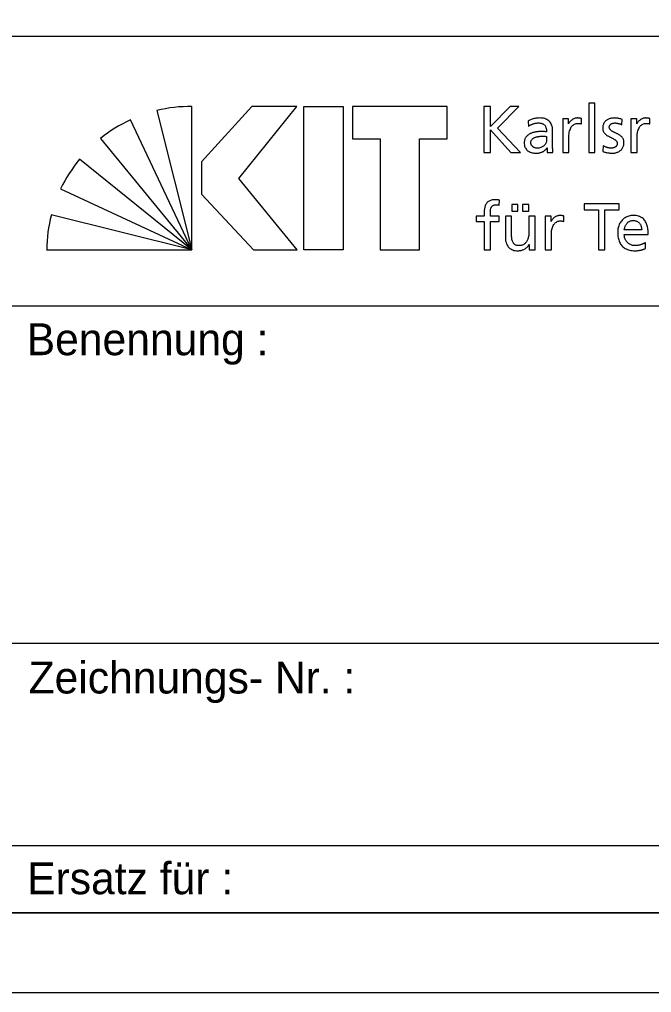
# Model space of a CAD drawing. Extents: x 0 to 297, y 0 to 210.
# Drawn here: x 275.16 to 285.08, y 0 to 15.26 of the extents above; entities that cross this region are included whole.
import ezdxf

# ---------------------------------------------------------------- set-up
doc = ezdxf.new("R2010")
doc.units = 0
doc.layers.add('90_Plankopf', color=7, linetype='Continuous')

msp = doc.modelspace()

# ---------------------------------------------------------------- linework, layer by layer
at = {"layer": '90_Plankopf'}
for p, q in [((251.53, 14.998), (296, 14.998)), ((251.53, 14.998), (296, 14.998)), ((277.87, 11.647), (277.87, 13.896)), ((282.452, 13.897), (282.452, 13.176)), ((277.319, 13.833), (277.87, 11.647)), ((277.87, 11.647), (276.908, 13.688)), ((283.145, 13.665), (283.15, 13.583)), ((283.982, 13.621), (283.982, 13.708)), ((284.614, 13.61), (284.622, 13.694)), ((285.053, 13.621), (285.053, 13.708)), ((283.53, 13.28), (283.53, 13.497)), ((276.436, 13.396), (277.87, 11.647)), ((283.433, 13.427), (283.433, 13.381)), ((284.324, 13.28), (284.319, 13.193)), ((282.452, 13.176), (282.556, 13.176)), ((282.876, 13.176), (283.027, 13.176)), ((277.87, 11.647), (276.108, 13.071)), ((275.81, 12.603), (277.87, 11.647)), ((282.693, 12.348), (282.697, 12.427)), ((277.87, 11.647), (275.664, 12.197)), ((283.707, 12.091), (283.707, 12.178)), ((284.927, 11.96), (284.654, 11.96)), ((284.654, 11.888), (285.03, 11.888)), ((284.989, 11.668), (284.989, 11.765)), ((275.591, 11.647), (277.87, 11.647)), ((275, 10.768), (296, 10.768)), ((275, 5.48), (296, 5.48)), ((275, 2.308), (296, 2.308)), ((296, 1.25), (251.53, 1.25)), ((254.45, 1.25), (296, 1.25)), ((254.45, 1.25), (296, 1.25))]:
    msp.add_line(p, q, dxfattribs=at)
for points in [[(0, 0), (297.25, 0), (297.25, 210.25), (0, 210.25)], [(6.25, 1.25), (296, 1.25), (296, 209), (6.25, 209)], [(279.517, 13.897), (278.809, 13.897), (278.018, 13.025), (278.018, 12.523), (278.834, 11.647), (279.521, 11.647), (278.606, 12.766)], [(280.243, 13.897), (280.243, 11.647), (279.625, 11.647), (279.625, 13.897)], [(280.391, 13.897), (280.391, 13.39), (280.825, 13.39), (280.825, 11.647), (281.443, 11.647), (281.443, 13.39), (281.877, 13.39), (281.877, 13.897)]]:
    msp.add_lwpolyline(points, close=True, dxfattribs=at)
for points in [[(283.027, 13.176), (282.662, 13.556), (283, 13.897), (282.863, 13.897), (282.556, 13.58), (282.556, 13.897), (282.452, 13.897)], [(284.095, 13.176), (284.192, 13.176), (284.192, 13.95), (284.095, 13.95), (284.095, 13.176)], [(283.78, 13.621), (283.778, 13.621), (283.778, 13.703), (283.688, 13.703), (283.688, 13.176), (283.785, 13.176), (283.785, 13.416)], [(284.852, 13.621), (284.85, 13.621), (284.85, 13.703), (284.759, 13.703), (284.759, 13.176), (284.856, 13.176), (284.856, 13.416)], [(282.556, 13.176), (282.556, 13.529), (282.876, 13.176)], [(283.441, 13.245), (283.443, 13.245), (283.443, 13.176), (283.534, 13.176)], [(284.248, 11.647), (284.351, 11.647), (284.351, 12.276), (284.575, 12.276), (284.575, 12.367), (284.024, 12.367), (284.024, 12.276), (284.248, 12.276), (284.248, 11.647)], [(282.456, 12.221), (282.456, 12.173), (282.332, 12.173), (282.332, 12.094), (282.456, 12.094), (282.456, 11.647), (282.553, 11.647), (282.553, 12.094), (282.692, 12.094), (282.692, 12.173), (282.553, 12.173), (282.553, 12.23)], [(282.889, 12.356), (282.889, 12.253), (282.986, 12.253), (282.986, 12.356), (282.889, 12.356)], [(283.058, 12.356), (283.058, 12.253), (283.155, 12.253), (283.155, 12.356), (283.058, 12.356)], [(282.885, 11.9), (282.885, 12.173), (282.788, 12.173), (282.788, 11.86)], [(283.254, 11.647), (283.254, 12.173), (283.157, 12.173), (283.157, 11.929)], [(283.506, 12.091), (283.504, 12.091), (283.504, 12.173), (283.413, 12.173), (283.413, 11.647), (283.51, 11.647), (283.51, 11.886)], [(283.158, 11.73), (283.16, 11.73), (283.16, 11.647), (283.254, 11.647)]]:
    msp.add_lwpolyline(points, dxfattribs=at)
for centre, start, end in [((277.862, 11.514), 89.8053, 103.1895), ((277.915, 11.529), 115.0126, 128.3968), ((277.954, 11.566), 140.7898, 154.174), ((277.973, 11.609), 165.7222, 179.1064)]:
    msp.add_arc(centre, 2.382, start, end, dxfattribs=at)
for points in [[(283.53, 13.497), (283.53, 13.545), (283.523, 13.585), (283.508, 13.617), (283.494, 13.65), (283.471, 13.674), (283.44, 13.69), (283.409, 13.707), (283.368, 13.715), (283.318, 13.715), (283.285, 13.715), (283.253, 13.71), (283.224, 13.701), (283.195, 13.692), (283.169, 13.68), (283.145, 13.665)], [(283.15, 13.583), (283.163, 13.594), (283.178, 13.604), (283.195, 13.611), (283.211, 13.62), (283.229, 13.626), (283.247, 13.63), (283.266, 13.634), (283.284, 13.637), (283.303, 13.637), (283.335, 13.637), (283.36, 13.631), (283.379, 13.621), (283.399, 13.611), (283.412, 13.596), (283.42, 13.575), (283.429, 13.555), (283.433, 13.53), (283.433, 13.499)], [(283.982, 13.708), (283.975, 13.709), (283.968, 13.71), (283.962, 13.712), (283.956, 13.713), (283.949, 13.713), (283.942, 13.714), (283.935, 13.715), (283.927, 13.715), (283.918, 13.715), (283.899, 13.715), (283.881, 13.711), (283.863, 13.703), (283.845, 13.695), (283.829, 13.684), (283.815, 13.67), (283.801, 13.656), (283.789, 13.639), (283.78, 13.621)], [(283.785, 13.416), (283.785, 13.46), (283.791, 13.498), (283.802, 13.53), (283.814, 13.562), (283.831, 13.587), (283.852, 13.604), (283.874, 13.621), (283.899, 13.63), (283.928, 13.63), (283.936, 13.631), (283.945, 13.63), (283.954, 13.629), (283.964, 13.627), (283.973, 13.625), (283.982, 13.621)], [(284.622, 13.694), (284.604, 13.7), (284.584, 13.705), (284.565, 13.709), (284.545, 13.713), (284.524, 13.715), (284.502, 13.715), (284.476, 13.715), (284.451, 13.712), (284.429, 13.705), (284.406, 13.698), (284.387, 13.688), (284.37, 13.675), (284.353, 13.662), (284.34, 13.645), (284.33, 13.625), (284.321, 13.604), (284.316, 13.58), (284.316, 13.553), (284.316, 13.532), (284.321, 13.514), (284.329, 13.498), (284.337, 13.483), (284.348, 13.47), (284.361, 13.459), (284.375, 13.447), (284.39, 13.437), (284.406, 13.429), (284.422, 13.42), (284.438, 13.412), (284.454, 13.404), (284.471, 13.397), (284.485, 13.389), (284.499, 13.38), (284.512, 13.373), (284.523, 13.363), (284.532, 13.353), (284.54, 13.343), (284.544, 13.331), (284.544, 13.318), (284.544, 13.304), (284.541, 13.292), (284.535, 13.282), (284.529, 13.272), (284.521, 13.265), (284.511, 13.259), (284.501, 13.253), (284.491, 13.249), (284.479, 13.246), (284.468, 13.244), (284.456, 13.242), (284.445, 13.242), (284.435, 13.242), (284.424, 13.244), (284.41, 13.247), (284.396, 13.249), (284.381, 13.253), (284.366, 13.259), (284.351, 13.265), (284.337, 13.271), (284.324, 13.28)], [(284.319, 13.193), (284.342, 13.181), (284.365, 13.174), (284.389, 13.17), (284.414, 13.166), (284.439, 13.164), (284.464, 13.164), (284.487, 13.164), (284.51, 13.167), (284.532, 13.174), (284.554, 13.18), (284.573, 13.191), (284.591, 13.204), (284.608, 13.217), (284.622, 13.234), (284.632, 13.255), (284.642, 13.276), (284.647, 13.3), (284.647, 13.328), (284.647, 13.352), (284.643, 13.372), (284.635, 13.389), (284.626, 13.406), (284.616, 13.42), (284.602, 13.431), (284.589, 13.443), (284.574, 13.453), (284.557, 13.461), (284.541, 13.469), (284.525, 13.477), (284.509, 13.484), (284.493, 13.491), (284.478, 13.499), (284.464, 13.507), (284.451, 13.515), (284.44, 13.524), (284.432, 13.534), (284.424, 13.545), (284.419, 13.557), (284.419, 13.573), (284.419, 13.587), (284.424, 13.599), (284.432, 13.609), (284.441, 13.618), (284.452, 13.625), (284.466, 13.63), (284.48, 13.634), (284.495, 13.637), (284.512, 13.637), (284.518, 13.637), (284.526, 13.636), (284.535, 13.634), (284.544, 13.633), (284.553, 13.631), (284.564, 13.628), (284.574, 13.626), (284.583, 13.623), (284.592, 13.62), (284.601, 13.616), (284.609, 13.613), (284.614, 13.61)], [(285.053, 13.708), (285.046, 13.709), (285.04, 13.71), (285.034, 13.712), (285.027, 13.713), (285.021, 13.713), (285.014, 13.714), (285.007, 13.715), (284.998, 13.715), (284.989, 13.715), (284.97, 13.715), (284.952, 13.711), (284.934, 13.703), (284.917, 13.695), (284.901, 13.684), (284.886, 13.67), (284.872, 13.656), (284.86, 13.639), (284.852, 13.621)], [(284.856, 13.416), (284.856, 13.46), (284.862, 13.498), (284.874, 13.53), (284.886, 13.562), (284.902, 13.587), (284.923, 13.604), (284.945, 13.621), (284.97, 13.63), (284.999, 13.63), (285.008, 13.631), (285.016, 13.63), (285.026, 13.629), (285.035, 13.627), (285.044, 13.625), (285.053, 13.621)], [(283.433, 13.499), (283.42, 13.5), (283.408, 13.501), (283.397, 13.501), (283.386, 13.501), (283.376, 13.501), (283.365, 13.501), (283.354, 13.501), (283.342, 13.501), (283.329, 13.501), (283.309, 13.501), (283.288, 13.5), (283.266, 13.496), (283.243, 13.492), (283.221, 13.487), (283.2, 13.478), (283.179, 13.47), (283.16, 13.46), (283.142, 13.446), (283.125, 13.433), (283.111, 13.416), (283.101, 13.397), (283.09, 13.377), (283.085, 13.354), (283.085, 13.328), (283.085, 13.29), (283.094, 13.259), (283.11, 13.235), (283.126, 13.211), (283.149, 13.193), (283.177, 13.181), (283.206, 13.17), (283.24, 13.164), (283.278, 13.164), (283.3, 13.164), (283.32, 13.167), (283.338, 13.172), (283.355, 13.177), (283.371, 13.184), (283.384, 13.192), (283.398, 13.2), (283.409, 13.209), (283.418, 13.218), (283.428, 13.228), (283.435, 13.236), (283.441, 13.245)], [(283.433, 13.381), (283.433, 13.354), (283.427, 13.331), (283.416, 13.31), (283.405, 13.289), (283.388, 13.273), (283.367, 13.261), (283.345, 13.249), (283.318, 13.243), (283.286, 13.242), (283.275, 13.242), (283.264, 13.244), (283.252, 13.248), (283.241, 13.252), (283.23, 13.257), (283.22, 13.264), (283.211, 13.272), (283.203, 13.281), (283.197, 13.291), (283.191, 13.302), (283.188, 13.314), (283.188, 13.328), (283.188, 13.347), (283.193, 13.362), (283.202, 13.374), (283.211, 13.387), (283.223, 13.396), (283.237, 13.404), (283.252, 13.411), (283.267, 13.417), (283.284, 13.42), (283.3, 13.424), (283.316, 13.426), (283.332, 13.428), (283.347, 13.429), (283.36, 13.429), (283.371, 13.429), (283.381, 13.429), (283.391, 13.429), (283.402, 13.428), (283.412, 13.428), (283.422, 13.427), (283.433, 13.427)], [(283.534, 13.176), (283.533, 13.181), (283.532, 13.188), (283.532, 13.197), (283.531, 13.205), (283.531, 13.216), (283.53, 13.23), (283.53, 13.243), (283.53, 13.26), (283.53, 13.28)], [(282.697, 12.427), (282.688, 12.428), (282.678, 12.43), (282.667, 12.431), (282.656, 12.432), (282.645, 12.433), (282.632, 12.433), (282.597, 12.433), (282.568, 12.428), (282.544, 12.418), (282.521, 12.408), (282.503, 12.394), (282.491, 12.375), (282.478, 12.356), (282.469, 12.334), (282.464, 12.308), (282.458, 12.282), (282.456, 12.253), (282.456, 12.221)], [(282.553, 12.23), (282.553, 12.247), (282.554, 12.264), (282.556, 12.279), (282.558, 12.294), (282.562, 12.307), (282.569, 12.319), (282.575, 12.33), (282.585, 12.339), (282.597, 12.345), (282.61, 12.351), (282.626, 12.354), (282.647, 12.354), (282.655, 12.354), (282.664, 12.354), (282.672, 12.353), (282.68, 12.352), (282.688, 12.35), (282.693, 12.348)], [(283.707, 12.178), (283.7, 12.179), (283.693, 12.181), (283.688, 12.182), (283.681, 12.183), (283.675, 12.184), (283.667, 12.184), (283.661, 12.185), (283.652, 12.185), (283.643, 12.185), (283.624, 12.185), (283.606, 12.181), (283.588, 12.173), (283.571, 12.165), (283.555, 12.154), (283.54, 12.14), (283.526, 12.126), (283.514, 12.11), (283.506, 12.091)], [(283.51, 11.886), (283.51, 11.93), (283.516, 11.968), (283.528, 12), (283.539, 12.032), (283.556, 12.057), (283.577, 12.074), (283.599, 12.092), (283.624, 12.1), (283.653, 12.1), (283.662, 12.101), (283.67, 12.1), (283.68, 12.099), (283.689, 12.097), (283.698, 12.095), (283.707, 12.091)], [(285.03, 11.888), (285.03, 11.931), (285.026, 11.97), (285.018, 12.006), (285.01, 12.042), (284.997, 12.073), (284.979, 12.1), (284.961, 12.127), (284.938, 12.148), (284.908, 12.162), (284.878, 12.177), (284.841, 12.185), (284.797, 12.185), (284.76, 12.185), (284.726, 12.178), (284.696, 12.166), (284.666, 12.152), (284.64, 12.134), (284.618, 12.111), (284.597, 12.087), (284.58, 12.059), (284.569, 12.026), (284.557, 11.994), (284.551, 11.958), (284.551, 11.919), (284.551, 11.876), (284.556, 11.837), (284.567, 11.802), (284.578, 11.767), (284.595, 11.737), (284.617, 11.712), (284.639, 11.687), (284.668, 11.668), (284.702, 11.655), (284.736, 11.641), (284.777, 11.634), (284.823, 11.634), (284.852, 11.634), (284.876, 11.636), (284.897, 11.64), (284.917, 11.644), (284.934, 11.648), (284.949, 11.653), (284.964, 11.659), (284.977, 11.664), (284.989, 11.668)], [(284.654, 11.96), (284.656, 11.977), (284.66, 11.995), (284.666, 12.012), (284.672, 12.029), (284.681, 12.045), (284.692, 12.059), (284.703, 12.073), (284.717, 12.085), (284.734, 12.093), (284.751, 12.102), (284.772, 12.107), (284.795, 12.107), (284.816, 12.107), (284.835, 12.103), (284.851, 12.095), (284.867, 12.088), (284.881, 12.077), (284.892, 12.064), (284.903, 12.05), (284.912, 12.035), (284.918, 12.017), (284.924, 11.999), (284.927, 11.981), (284.927, 11.96)], [(283.157, 11.929), (283.157, 11.897), (283.154, 11.868), (283.147, 11.841), (283.141, 11.815), (283.131, 11.792), (283.118, 11.773), (283.105, 11.754), (283.088, 11.739), (283.068, 11.728), (283.048, 11.718), (283.024, 11.713), (282.997, 11.713), (282.969, 11.714), (282.947, 11.722), (282.93, 11.736), (282.914, 11.75), (282.902, 11.771), (282.895, 11.798), (282.889, 11.825), (282.885, 11.859), (282.885, 11.9)], [(282.788, 11.86), (282.788, 11.813), (282.795, 11.772), (282.809, 11.739), (282.823, 11.705), (282.845, 11.679), (282.874, 11.661), (282.903, 11.644), (282.94, 11.634), (282.986, 11.634), (283.01, 11.634), (283.034, 11.638), (283.056, 11.646), (283.079, 11.653), (283.099, 11.665), (283.117, 11.679), (283.134, 11.693), (283.148, 11.71), (283.158, 11.73)], [(284.989, 11.765), (284.983, 11.76), (284.975, 11.755), (284.963, 11.749), (284.952, 11.743), (284.939, 11.737), (284.924, 11.732), (284.909, 11.726), (284.893, 11.722), (284.876, 11.718), (284.86, 11.715), (284.844, 11.713), (284.827, 11.713), (284.804, 11.713), (284.782, 11.717), (284.762, 11.725), (284.741, 11.734), (284.722, 11.746), (284.706, 11.761), (284.69, 11.777), (284.677, 11.795), (284.668, 11.817), (284.659, 11.838), (284.654, 11.862), (284.654, 11.888)]]:
    msp.add_open_spline(points, degree=3, dxfattribs=at)

# ---------------------------------------------------------------- texts
for s, p in [('Benennung :', (275.278, 9.995)), ('Zeichnungs- Nr. :', (275.307, 4.69)), ('Ersatz für :', (275.285, 1.542))]:
    msp.add_text(s, height=0.5, dxfattribs=at).set_placement(p)

doc.saveas('drawing.dxf')
